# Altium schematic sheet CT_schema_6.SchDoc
size 451 x 443 mm
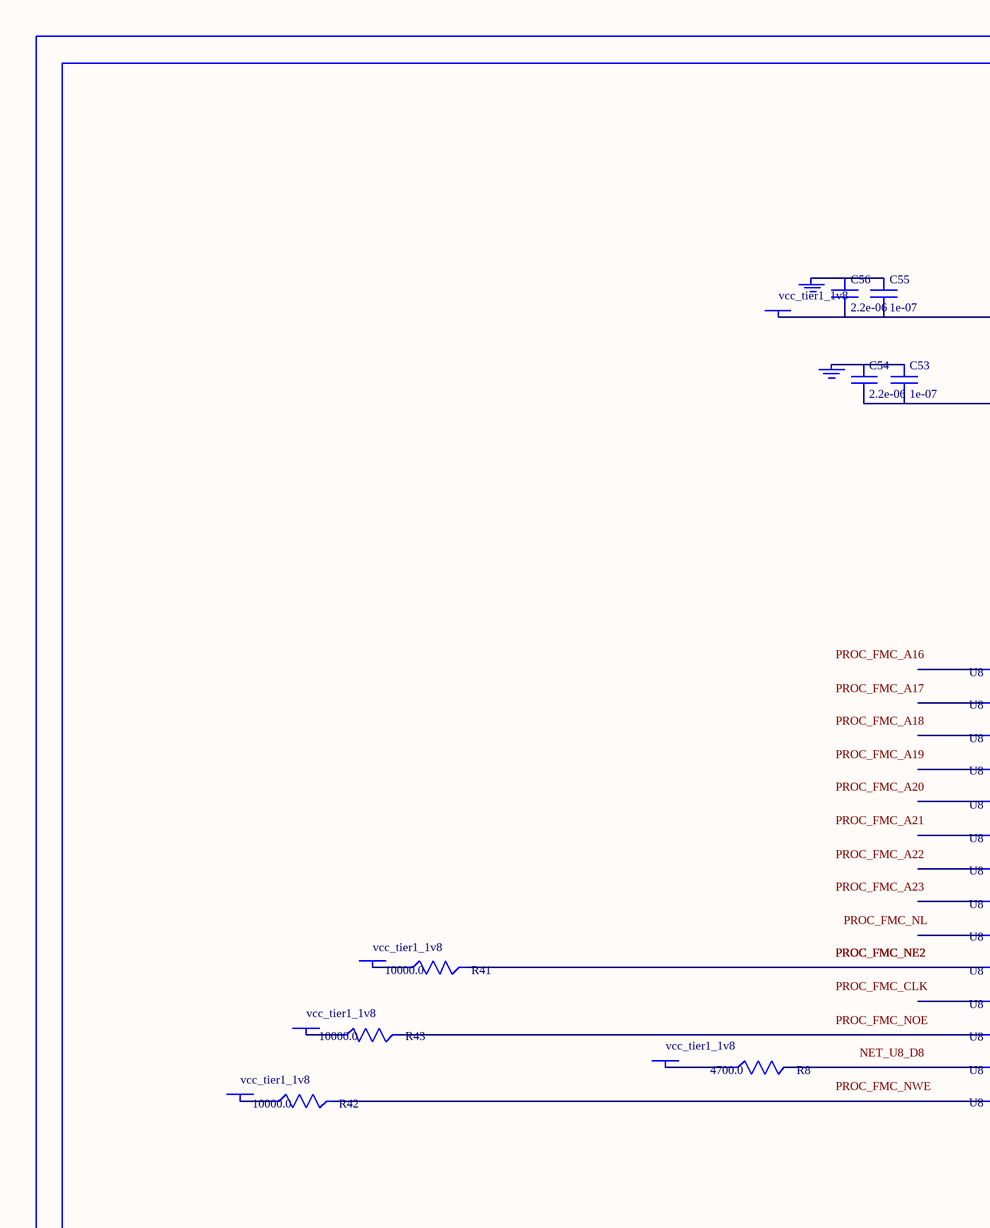
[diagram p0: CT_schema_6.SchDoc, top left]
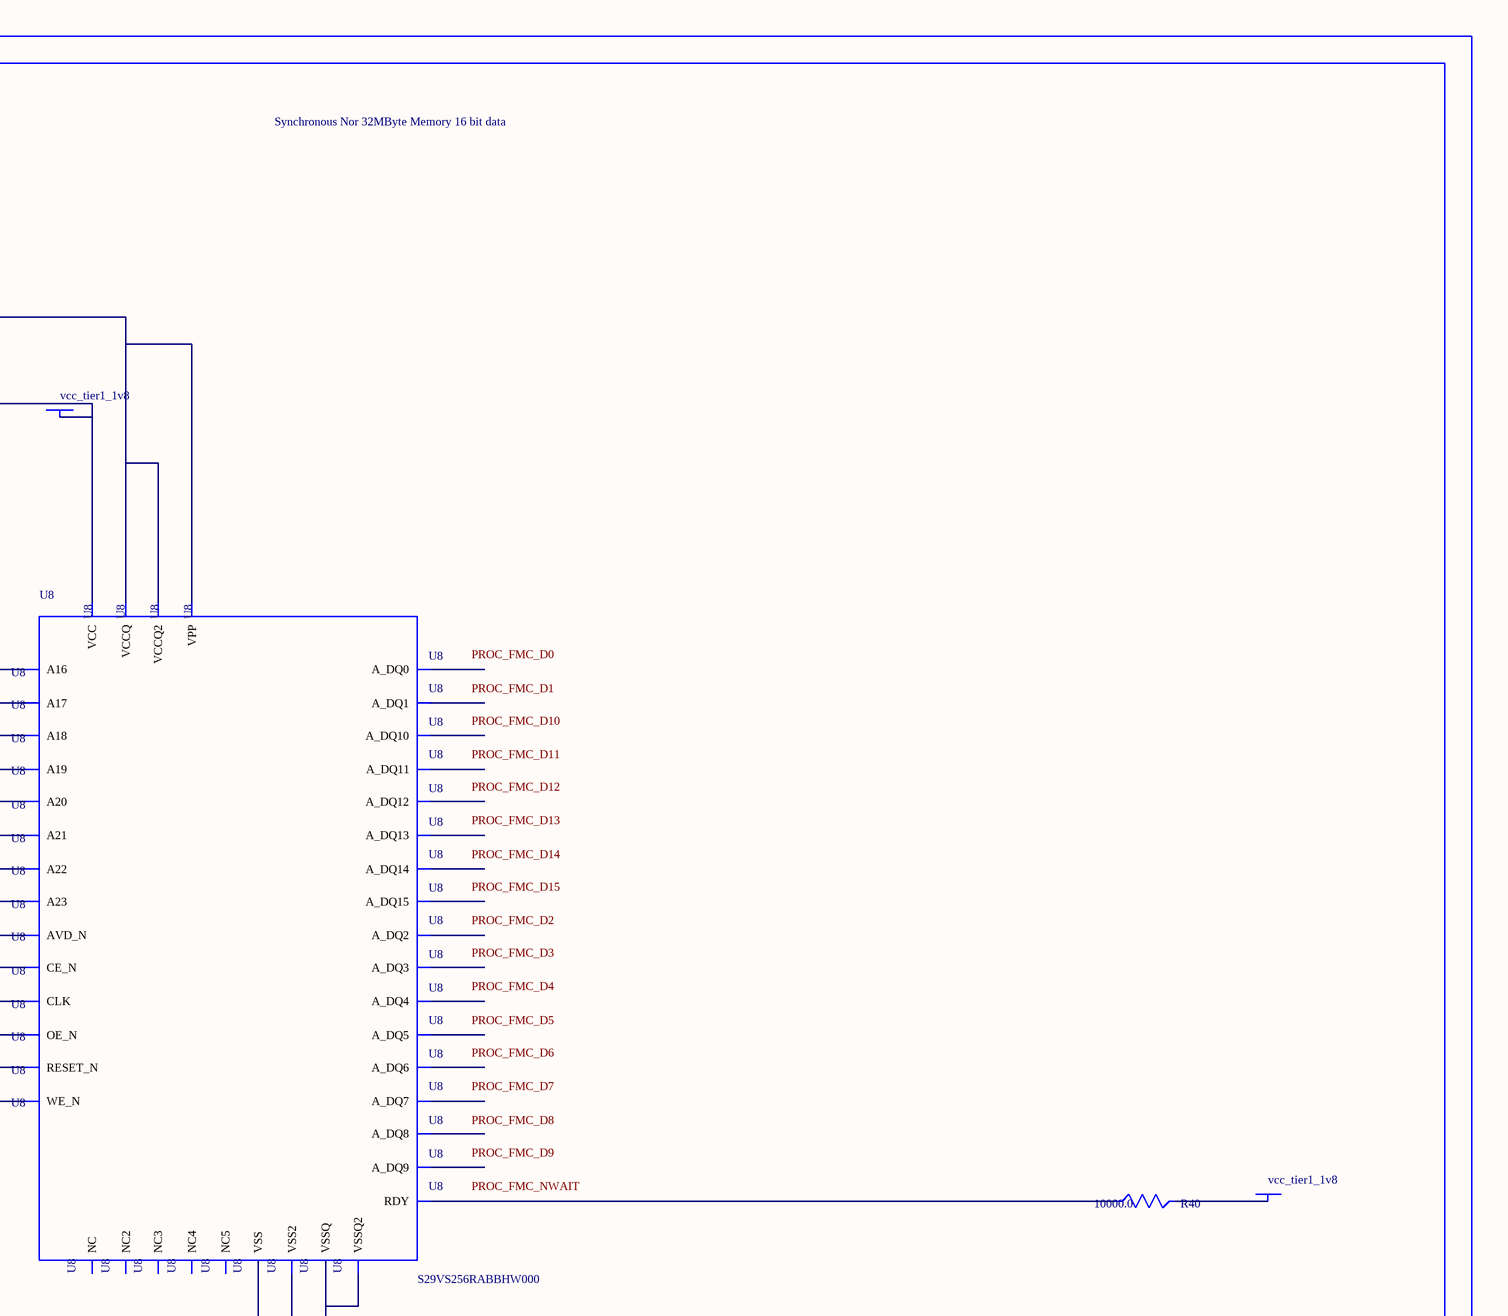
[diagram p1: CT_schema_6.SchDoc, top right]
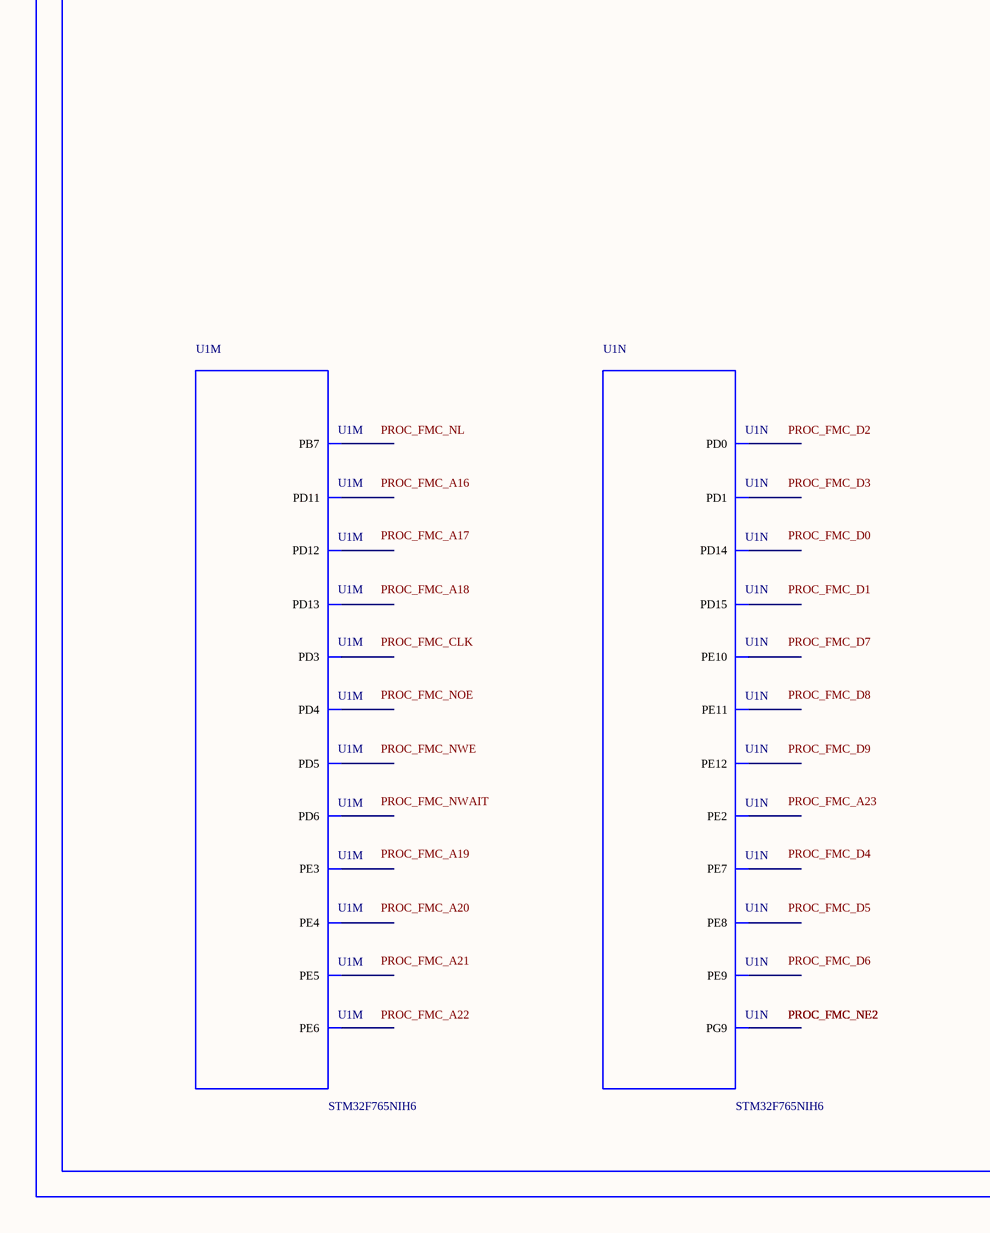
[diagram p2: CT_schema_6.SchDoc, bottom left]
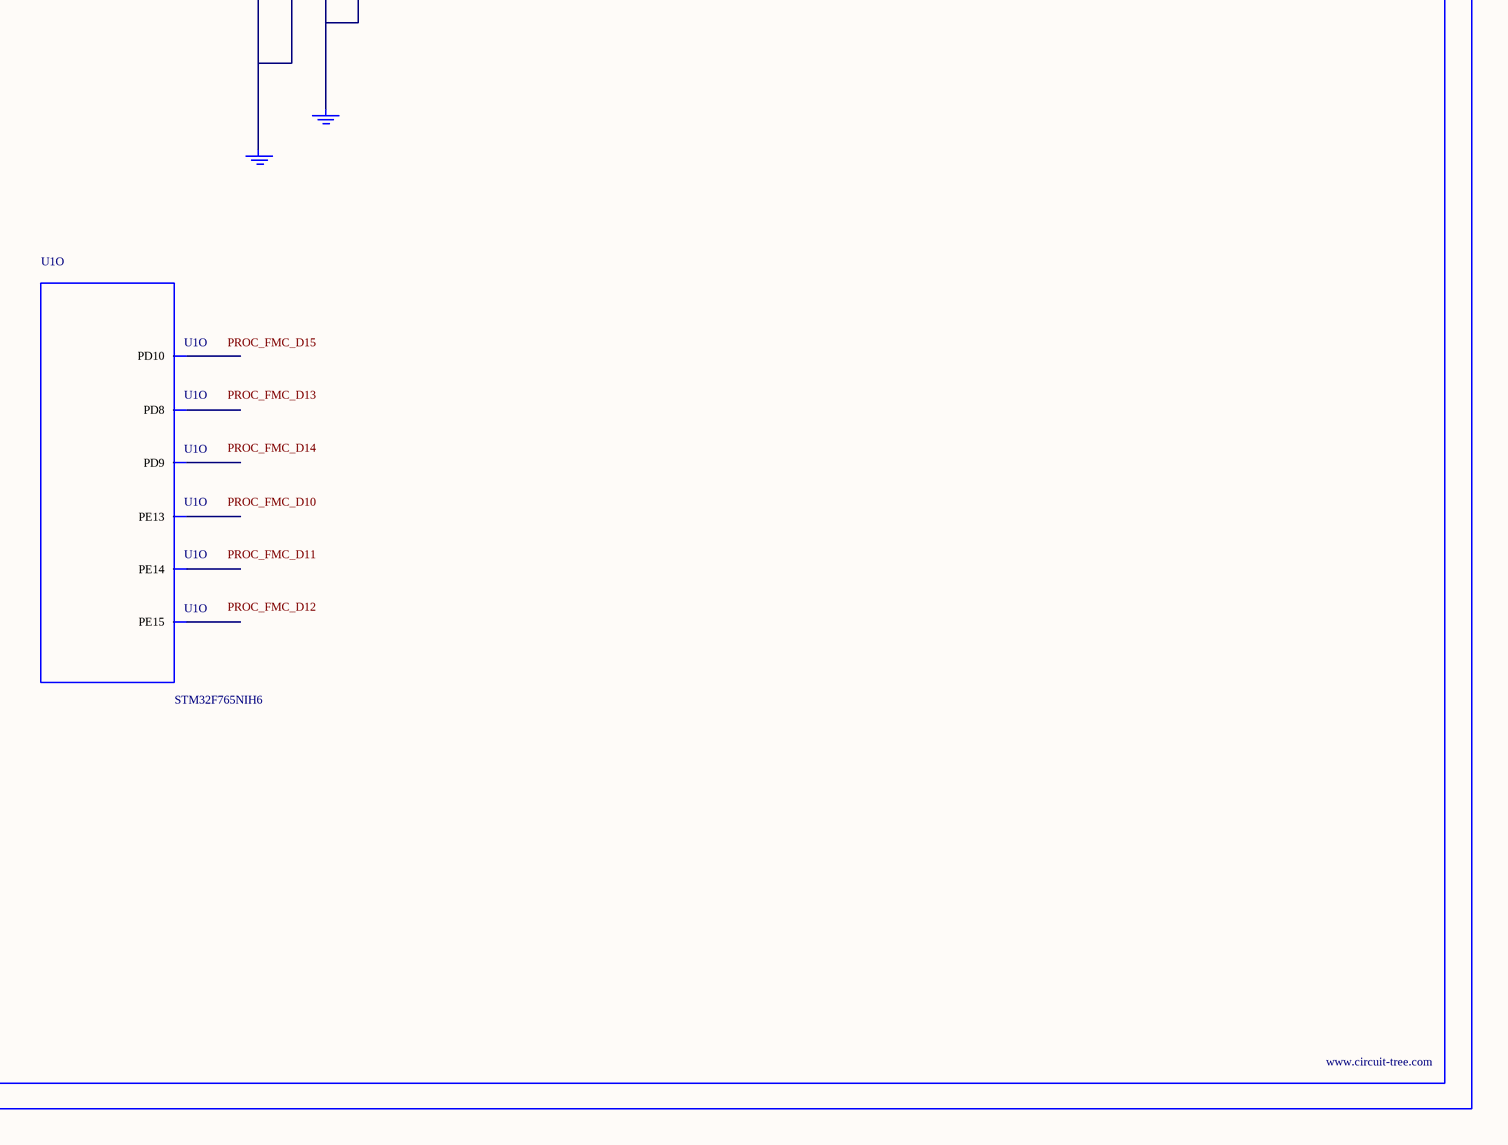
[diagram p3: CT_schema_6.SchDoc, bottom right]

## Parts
BORDER5  (no value)
C53  1e-07  [C0402]
C54  2.2e-06  [C0603]
C55  1e-07  [C0402]
C56  2.2e-06  [C0603]
GND_INSTANCE_5_0  (no value)
GND_INSTANCE_5_1  (no value)
GND_INSTANCE_5_2  (no value)
GND_INSTANCE_5_3  (no value)
POWER_INSTANCE_5_0  vcc_tier1_1v8
POWER_INSTANCE_5_1  vcc_tier1_1v8
POWER_INSTANCE_5_2  vcc_tier1_1v8
POWER_INSTANCE_5_3  vcc_tier1_1v8
POWER_INSTANCE_5_4  vcc_tier1_1v8
POWER_INSTANCE_5_5  vcc_tier1_1v8
POWER_INSTANCE_5_6  vcc_tier1_1v8
R8  4700.0  [R0603]
R40  10000.0  [R0603]
R41  10000.0  [R0603]
R42  10000.0  [R0603]
R43  10000.0  [R0603]
U1  STM32F765NIH6  [TFBGA216]  (parts M,N,O of 15)
U8  S29VS256RABBHW000  [S29VS256RABBHW000]

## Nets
NetC53_1: C53.1 C54.1 GND_INSTANCE_5_0.0(GND)
NetC53_2: C53.2 C54.2 POWER_INSTANCE_5_0.0(PWR) U8.C7(VCC)
NetC55_1: C55.1 C56.1 GND_INSTANCE_5_1.0(GND)
NetC55_2: C55.2 C56.2 POWER_INSTANCE_5_1.0(PWR) U8.C9(VPP) U8.D3(VCCQ) U8.F10(VCCQ2)
NetGND_INSTANCE_5_2_0: GND_INSTANCE_5_2.0(GND) U8.C5(VSS) U8.D12(VSS2)
NetGND_INSTANCE_5_3_0: GND_INSTANCE_5_3.0(GND) U8.E3(VSSQ) U8.F5(VSSQ2)
NetPOWER_INSTANCE_5_2_0: POWER_INSTANCE_5_2.0(PWR) R40.2
NetPOWER_INSTANCE_5_3_0: POWER_INSTANCE_5_3.0(PWR) R41.1
NetPOWER_INSTANCE_5_4_0: POWER_INSTANCE_5_4.0(PWR) R42.1
NetPOWER_INSTANCE_5_5_0: POWER_INSTANCE_5_5.0(PWR) R43.1
NetPOWER_INSTANCE_5_6_0: POWER_INSTANCE_5_6.0(PWR) R8.1
NetR8_2: R8.2 U8.D8(RESET_N)
NetR40_1: R40.1 U8.C3(RDY)
NetR41_2: R41.2 U8.D11(CE_N)
NetR42_2: R42.2 U8.C8(WE_N)
NetR43_2: R43.2 U8.E12(OE_N)

Not connected (* = marked no-connect by the designer): U1 A1(PE4) A2(PE3) A3(PE2) B1(PE5) B2(PE6) B5(PB7) B11(PD6) B12(PD0) C10(PD5) C11(PD3) C12(PD1) D9(PG9) D11(PD4) K13(PD15) K15(PD10) L12(PD14) L14(PD9) L15(PD8) M10(PD12) M11(PD13) N9(PE8) N10(PD11) P9(PE9) P10(PE11) P11(PE14) R8(PE7) R9(PE10) R10(PE12) R11(PE15) R12(PE13); U8 A1(NC) A14(NC2) C4(A21) C6(CLK) C10(A19) C11(A17) C12(A22) D4(A16) D5(A20) D6(AVD_N) D7(A23) D9(NC3) D10(A18) E4(A_DQ8) E5(A_DQ9) E6(A_DQ2) E7(A_DQ3) E8(A_DQ12) E9(A_DQ13) E10(A_DQ6) E11(A_DQ7) F3(A_DQ0) F4(A_DQ1) F6(A_DQ10) F7(A_DQ11) F8(A_DQ4) F9(A_DQ5) F11(A_DQ14) F12(A_DQ15) H1(NC4) H14(NC5)

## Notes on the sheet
- Labels drawn without touching a wire or pin: NET_U8_D8, PROC_FMC_A16, PROC_FMC_A17, PROC_FMC_A18, PROC_FMC_A19, PROC_FMC_A20, PROC_FMC_A21, PROC_FMC_A22, PROC_FMC_A23, PROC_FMC_CLK, PROC_FMC_D0, PROC_FMC_D1, PROC_FMC_D2, PROC_FMC_D3, PROC_FMC_D4, PROC_FMC_D5, PROC_FMC_D6, PROC_FMC_D7, PROC_FMC_D8, PROC_FMC_D9, PROC_FMC_D10, PROC_FMC_D11, PROC_FMC_D12, PROC_FMC_D13, PROC_FMC_D14, PROC_FMC_D15, PROC_FMC_NL, PROC_FMC_NOE, PROC_FMC_NWAIT, PROC_FMC_NWE

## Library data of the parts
BORDER5 = BORDER_PAGE5
C53 C55 = C0402C104K3RACTU
C54 C56 = C0603C225K8RACTU
GND_INSTANCE_5_0-GND_INSTANCE_5_3 = GND
POWER_INSTANCE_5_0-POWER_INSTANCE_5_6 = PWR
R8 = RC0603JR-074K7L
R40-R43 = RC0603JR-0710KL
